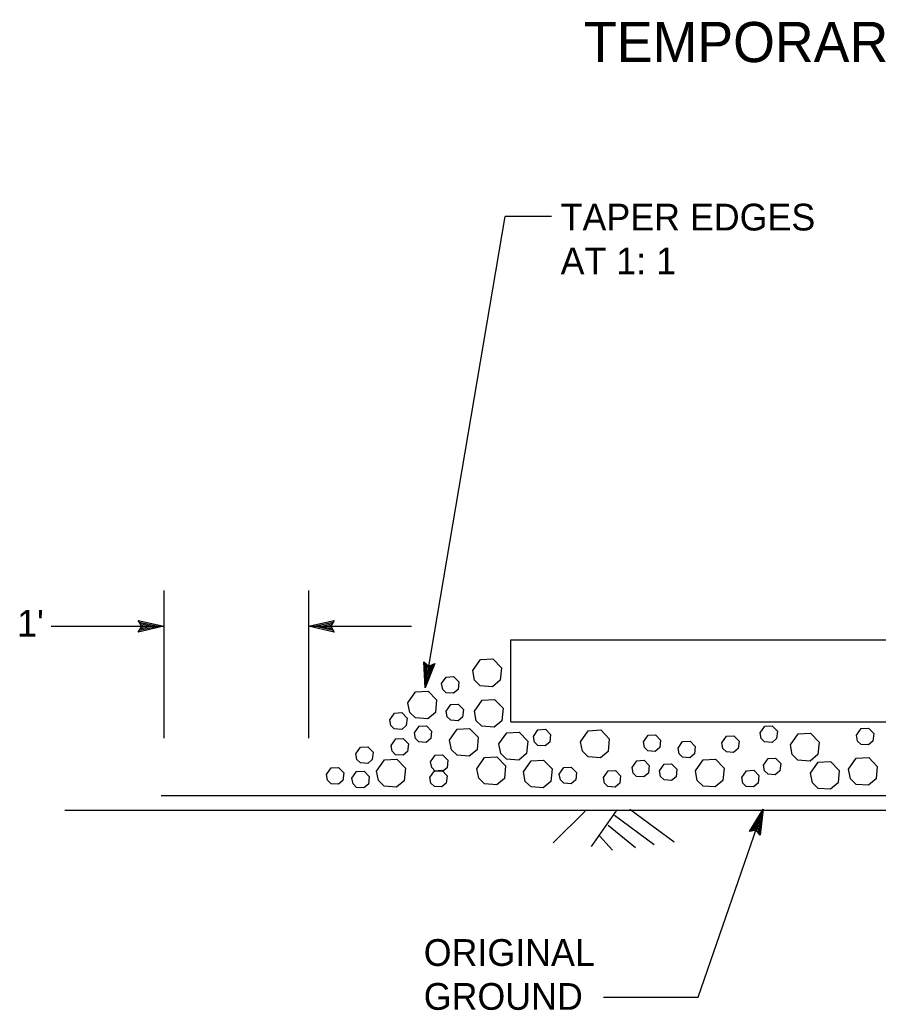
# Model space of a CAD drawing. Extents: x 6709491 to 6710959, y 1869789 to 1870763.
# Drawn here: x 6709492.7 to 6709685, y 1869799.3 to 1870021.3 of the extents above; entities that cross this region are included whole.
import ezdxf

# ---------------------------------------------------------------- set-up
doc = ezdxf.new("R2010")
doc.units = 0
for name, color, linetype in [('56 Stg 3 Anno', 7, 'Continuous'), ('57 Undefined', 7, 'Continuous'), ('59 Soundwall Ann', 7, 'Continuous'), ('60 Nongeo Data', 7, 'Continuous')]:
    doc.layers.add(name, color=color, linetype=linetype)

msp = doc.modelspace()

# ---------------------------------------------------------------- linework, layer by layer
at = {"layer": '56 Stg 3 Anno'}
for p, q in [((6709583.47, 1869871.52), (6709601.41, 1869977.17)), ((6709611.8, 1869977.17), (6709601.41, 1869977.17)), ((6709524.96, 1869893.38), (6709524.96, 1869860.25)), ((6709557.38, 1869893.38), (6709557.38, 1869860.25)), ((6709499.65, 1869885.34), (6709524.96, 1869885.34)), ((6709519.97, 1869885.34), (6709519.2, 1869886.62)), ((6709519.2, 1869886.62), (6709519.2, 1869886.62)), ((6709519.2, 1869886.62), (6709524.96, 1869885.34)), ((6709524.96, 1869885.34), (6709519.2, 1869884.06)), ((6709519.2, 1869884.06), (6709519.97, 1869885.34)), ((6709519.41, 1869886.28), (6709523.64, 1869885.34)), ((6709523.63, 1869885.33), (6709519.43, 1869884.4)), ((6709522.31, 1869885.34), (6709519.6, 1869884.74)), ((6709519.64, 1869885.94), (6709522.31, 1869885.34)), ((6709519.81, 1869885.6), (6709520.99, 1869885.34)), ((6709520.99, 1869885.34), (6709519.82, 1869885.08)), ((6709524.96, 1869885.34), (6709524.96, 1869885.34)), ((6709557.38, 1869885.34), (6709563.14, 1869886.61)), ((6709557.38, 1869885.34), (6709580.43, 1869885.34)), ((6709563.14, 1869884.05), (6709557.38, 1869885.34)), ((6709557.38, 1869885.34), (6709557.38, 1869885.34)), ((6709562.94, 1869884.39), (6709558.71, 1869885.34)), ((6709558.72, 1869885.34), (6709562.92, 1869886.27)), ((6709560.04, 1869885.33), (6709562.75, 1869885.94)), ((6709562.71, 1869884.74), (6709560.04, 1869885.33)), ((6709561.36, 1869885.33), (6709562.52, 1869885.59)), ((6709562.54, 1869885.07), (6709561.36, 1869885.33)), ((6709563.14, 1869886.61), (6709562.38, 1869885.34)), ((6709562.38, 1869885.34), (6709563.14, 1869884.05)), ((6709563.14, 1869886.61), (6709563.14, 1869886.61)), ((6709519.2, 1869884.06), (6709519.2, 1869884.06)), ((6709563.14, 1869884.05), (6709563.14, 1869884.05)), ((6709583.47, 1869871.52), (6709583.17, 1869877.41)), ((6709583.17, 1869877.41), (6709583.17, 1869877.41)), ((6709583.17, 1869877.41), (6709584.3, 1869876.44)), ((6709585.7, 1869876.99), (6709583.47, 1869871.52)), ((6709583.69, 1869872.84), (6709583.48, 1869877.13)), ((6709585.33, 1869876.84), (6709583.69, 1869872.83)), ((6709583.91, 1869874.14), (6709583.78, 1869876.91)), ((6709584.95, 1869876.67), (6709583.91, 1869874.14)), ((6709584.14, 1869875.44), (6709584.08, 1869876.63)), ((6709584.6, 1869876.56), (6709584.14, 1869875.44)), ((6709584.3, 1869876.44), (6709585.7, 1869876.99)), ((6709585.7, 1869876.99), (6709585.7, 1869876.99)), ((6709583.47, 1869871.52), (6709583.47, 1869871.52)), ((6709644.67, 1869802.22), (6709659.29, 1869844.37)), ((6709656.19, 1869839.35), (6709659.29, 1869844.37)), ((6709656.58, 1869839.44), (6709658.85, 1869843.12)), ((6709658.85, 1869843.11), (6709658.36, 1869838.84)), ((6709659.29, 1869844.37), (6709658.61, 1869838.51)), ((6709659.29, 1869844.37), (6709659.29, 1869844.37)), ((6709656.98, 1869839.54), (6709658.42, 1869841.87)), ((6709658.42, 1869841.87), (6709658.1, 1869839.11)), ((6709657.65, 1869839.66), (6709656.19, 1869839.35)), ((6709656.19, 1869839.35), (6709656.19, 1869839.35)), ((6709657.35, 1869839.59), (6709657.98, 1869840.62)), ((6709658.61, 1869838.51), (6709657.65, 1869839.66)), ((6709657.98, 1869840.62), (6709657.84, 1869839.44)), ((6709658.61, 1869838.51), (6709658.61, 1869838.51)), ((6709623.47, 1869802.22), (6709644.67, 1869802.22))]:
    msp.add_line(p, q, dxfattribs=at)
at = {"layer": '59 Soundwall Ann'}
for p, q in [((6709619.34, 1869843.9), (6709612.17, 1869836.78)), ((6709626.49, 1869844.23), (6709620.7, 1869835.99)), ((6709629.39, 1869844.36), (6709639.34, 1869837.03)), ((6709625.94, 1869843.01), (6709634.84, 1869836.46)), ((6709624.5, 1869840.75), (6709630.61, 1869835.77)), ((6709622.56, 1869838.37), (6709625.47, 1869835.17))]:
    msp.add_line(p, q, dxfattribs=at)
at = {"layer": '60 Nongeo Data'}
for p, q in [((6709602.72, 1869863.92), (6709602.72, 1869882.28)), ((6709602.72, 1869882.28), (6709947.32, 1869882.28)), ((6709602.72, 1869863.92), (6709756.24, 1869863.92)), ((6709524.37, 1869847.39), (6709755.52, 1869847.39)), ((6709502.72, 1869844.14), (6709754.44, 1869844.14))]:
    msp.add_line(p, q, dxfattribs=at)
for points in [[(6709594.15, 1869875.41), (6709595.89, 1869877.88), (6709598.67, 1869878.04), (6709600.6, 1869876.04), (6709600.32, 1869873.24), (6709598.6, 1869871.81), (6709595.86, 1869872.01), (6709594.57, 1869873.26), (6709594.15, 1869875.41)], [(6709587.18, 1869872.5), (6709588.23, 1869873.98), (6709589.89, 1869874.08), (6709591.05, 1869872.87), (6709590.88, 1869871.19), (6709589.85, 1869870.34), (6709588.21, 1869870.45), (6709587.43, 1869871.2), (6709587.18, 1869872.5)], [(6709579.62, 1869868.2), (6709581.36, 1869870.67), (6709584.14, 1869870.83), (6709586.07, 1869868.83), (6709585.79, 1869866.02), (6709584.07, 1869864.6), (6709581.33, 1869864.8), (6709580.04, 1869866.05), (6709579.62, 1869868.2)], [(6709588.2, 1869866.31), (6709589.24, 1869867.8), (6709590.91, 1869867.89), (6709592.07, 1869866.69), (6709591.9, 1869865.01), (6709590.87, 1869864.15), (6709589.22, 1869864.27), (6709588.45, 1869865.02), (6709588.2, 1869866.31)], [(6709594.53, 1869866.33), (6709596.27, 1869868.81), (6709599.04, 1869868.97), (6709600.98, 1869866.97), (6709600.7, 1869864.16), (6709598.98, 1869862.73), (6709596.24, 1869862.93), (6709594.95, 1869864.18), (6709594.53, 1869866.33)], [(6709575.57, 1869864.41), (6709576.61, 1869865.89), (6709578.28, 1869865.99), (6709579.44, 1869864.78), (6709579.27, 1869863.1), (6709578.24, 1869862.25), (6709576.59, 1869862.36), (6709575.82, 1869863.11), (6709575.57, 1869864.41)], [(6709581.08, 1869861.48), (6709582.13, 1869862.97), (6709583.79, 1869863.06), (6709584.95, 1869861.86), (6709584.78, 1869860.18), (6709583.76, 1869859.32), (6709582.11, 1869859.44), (6709581.34, 1869860.19), (6709581.09, 1869861.48)], [(6709658.57, 1869861.48), (6709659.61, 1869862.97), (6709661.28, 1869863.06), (6709662.44, 1869861.86), (6709662.27, 1869860.18), (6709661.24, 1869859.32), (6709659.59, 1869859.44), (6709658.82, 1869860.19), (6709658.57, 1869861.48)], [(6709588.95, 1869859.84), (6709590.69, 1869862.31), (6709593.46, 1869862.47), (6709595.39, 1869860.47), (6709595.12, 1869857.66), (6709593.4, 1869856.23), (6709590.66, 1869856.43), (6709589.37, 1869857.69), (6709588.95, 1869859.84)], [(6709600.04, 1869858.97), (6709601.78, 1869861.44), (6709604.56, 1869861.6), (6709606.49, 1869859.6), (6709606.21, 1869856.8), (6709604.5, 1869855.37), (6709601.75, 1869855.57), (6709600.46, 1869856.82), (6709600.05, 1869858.97)], [(6709607.75, 1869860.68), (6709608.79, 1869862.16), (6709610.46, 1869862.26), (6709611.61, 1869861.06), (6709611.45, 1869859.38), (6709610.42, 1869858.52), (6709608.77, 1869858.64), (6709608, 1869859.39), (6709607.75, 1869860.68)], [(6709618.33, 1869859.48), (6709620.07, 1869861.95), (6709622.84, 1869862.11), (6709624.77, 1869860.11), (6709624.5, 1869857.3), (6709622.78, 1869855.88), (6709620.04, 1869856.08), (6709618.75, 1869857.33), (6709618.33, 1869859.48)], [(6709632.41, 1869859.47), (6709633.45, 1869860.95), (6709635.12, 1869861.05), (6709636.27, 1869859.85), (6709636.11, 1869858.16), (6709635.08, 1869857.31), (6709633.43, 1869857.43), (6709632.66, 1869858.18), (6709632.41, 1869859.47)], [(6709649.97, 1869859.24), (6709651.01, 1869860.73), (6709652.68, 1869860.82), (6709653.84, 1869859.62), (6709653.67, 1869857.94), (6709652.64, 1869857.08), (6709651, 1869857.2), (6709650.22, 1869857.95), (6709649.97, 1869859.24)], [(6709665.35, 1869858.75), (6709667.09, 1869861.23), (6709669.87, 1869861.39), (6709671.8, 1869859.38), (6709671.52, 1869856.58), (6709669.8, 1869855.15), (6709667.06, 1869855.35), (6709665.77, 1869856.6), (6709665.35, 1869858.75)], [(6709680.16, 1869860.93), (6709681.21, 1869862.41), (6709682.87, 1869862.51), (6709684.03, 1869861.3), (6709683.86, 1869859.62), (6709682.84, 1869858.77), (6709681.19, 1869858.88), (6709680.42, 1869859.63), (6709680.17, 1869860.93)], [(6709575.87, 1869858.61), (6709576.91, 1869860.1), (6709578.58, 1869860.19), (6709579.74, 1869858.99), (6709579.57, 1869857.31), (6709578.54, 1869856.45), (6709576.89, 1869856.57), (6709576.12, 1869857.32), (6709575.87, 1869858.61)], [(6709640.17, 1869858.04), (6709641.21, 1869859.52), (6709642.88, 1869859.62), (6709644.04, 1869858.42), (6709643.87, 1869856.74), (6709642.84, 1869855.88), (6709641.19, 1869856), (6709640.42, 1869856.75), (6709640.17, 1869858.04)], [(6709567.96, 1869856.78), (6709569, 1869858.26), (6709570.67, 1869858.36), (6709571.83, 1869857.16), (6709571.66, 1869855.48), (6709570.63, 1869854.62), (6709568.99, 1869854.74), (6709568.21, 1869855.49), (6709567.96, 1869856.78)], [(6709584.71, 1869854.95), (6709585.75, 1869856.44), (6709587.42, 1869856.53), (6709588.58, 1869855.33), (6709588.41, 1869853.65), (6709587.38, 1869852.79), (6709585.74, 1869852.91), (6709584.96, 1869853.66), (6709584.71, 1869854.95)], [(6709572.62, 1869852.91), (6709574.36, 1869855.39), (6709577.13, 1869855.55), (6709579.07, 1869853.54), (6709578.79, 1869850.74), (6709577.07, 1869849.31), (6709574.33, 1869849.51), (6709573.04, 1869850.76), (6709572.62, 1869852.91)], [(6709595.08, 1869853.42), (6709596.82, 1869855.9), (6709599.59, 1869856.06), (6709601.52, 1869854.06), (6709601.25, 1869851.25), (6709599.53, 1869849.82), (6709596.79, 1869850.02), (6709595.5, 1869851.27), (6709595.08, 1869853.42)], [(6709605.52, 1869852.73), (6709607.26, 1869855.2), (6709610.04, 1869855.36), (6709611.97, 1869853.36), (6709611.69, 1869850.55), (6709609.98, 1869849.13), (6709607.23, 1869849.33), (6709605.94, 1869850.58), (6709605.52, 1869852.73)], [(6709629.87, 1869853.73), (6709630.91, 1869855.21), (6709632.58, 1869855.31), (6709633.74, 1869854.11), (6709633.57, 1869852.42), (6709632.54, 1869851.57), (6709630.89, 1869851.68), (6709630.12, 1869852.44), (6709629.87, 1869853.73)], [(6709636.03, 1869852.94), (6709637.08, 1869854.42), (6709638.74, 1869854.52), (6709639.9, 1869853.32), (6709639.73, 1869851.63), (6709638.7, 1869850.78), (6709637.06, 1869850.9), (6709636.28, 1869851.65), (6709636.03, 1869852.94)], [(6709644.06, 1869852.94), (6709645.8, 1869855.41), (6709648.58, 1869855.57), (6709650.51, 1869853.57), (6709650.23, 1869850.76), (6709648.51, 1869849.34), (6709645.77, 1869849.54), (6709644.48, 1869850.79), (6709644.06, 1869852.94)], [(6709659.31, 1869854.23), (6709660.36, 1869855.71), (6709662.02, 1869855.81), (6709663.18, 1869854.61), (6709663.01, 1869852.93), (6709661.98, 1869852.07), (6709660.34, 1869852.19), (6709659.56, 1869852.94), (6709659.31, 1869854.23)], [(6709669.86, 1869852.42), (6709671.6, 1869854.9), (6709674.38, 1869855.06), (6709676.31, 1869853.06), (6709676.03, 1869850.25), (6709674.32, 1869848.82), (6709671.57, 1869849.02), (6709670.28, 1869850.27), (6709669.86, 1869852.42)], [(6709678.39, 1869853.31), (6709680.13, 1869855.78), (6709682.9, 1869855.94), (6709684.83, 1869853.94), (6709684.55, 1869851.13), (6709682.84, 1869849.71), (6709680.1, 1869849.9), (6709678.81, 1869851.16), (6709678.39, 1869853.31)], [(6709561.38, 1869852.11), (6709562.42, 1869853.59), (6709564.09, 1869853.69), (6709565.25, 1869852.49), (6709565.08, 1869850.8), (6709564.05, 1869849.95), (6709562.41, 1869850.07), (6709561.63, 1869850.82), (6709561.38, 1869852.11)], [(6709567.1, 1869851.29), (6709568.14, 1869852.77), (6709569.81, 1869852.87), (6709570.97, 1869851.66), (6709570.8, 1869849.98), (6709569.77, 1869849.13), (6709568.13, 1869849.24), (6709567.35, 1869850), (6709567.1, 1869851.29)], [(6709584.54, 1869851.49), (6709585.58, 1869852.97), (6709587.25, 1869853.07), (6709588.41, 1869851.86), (6709588.24, 1869850.18), (6709587.21, 1869849.33), (6709585.56, 1869849.44), (6709584.79, 1869850.2), (6709584.54, 1869851.49)], [(6709613.55, 1869852.21), (6709614.59, 1869853.7), (6709616.26, 1869853.79), (6709617.42, 1869852.59), (6709617.25, 1869850.91), (6709616.22, 1869850.05), (6709614.57, 1869850.17), (6709613.8, 1869850.92), (6709613.55, 1869852.21)], [(6709623.44, 1869851.45), (6709624.49, 1869852.94), (6709626.15, 1869853.03), (6709627.31, 1869851.83), (6709627.14, 1869850.15), (6709626.11, 1869849.29), (6709624.47, 1869849.41), (6709623.7, 1869850.16), (6709623.44, 1869851.45)], [(6709654.45, 1869851.49), (6709655.5, 1869852.97), (6709657.16, 1869853.07), (6709658.32, 1869851.87), (6709658.15, 1869850.18), (6709657.12, 1869849.33), (6709655.48, 1869849.44), (6709654.71, 1869850.2), (6709654.45, 1869851.49)]]:
    msp.add_lwpolyline(points, dxfattribs=at)

# ---------------------------------------------------------------- texts
at = {"layer": '57 Undefined'}
for s, height, p in [('TEMPORARY CONSTRUCTION ENTRANCE (TYPE 2)', 9, (6709619.09, 1870011.81)), ('TAPER EDGES', 6, (6709613.86, 1869974.07)), ('AT 1: 1', 6, (6709613.86, 1869964.23)), ("1'", 6, (6709492.05, 1869883.02)), ('ORIGINAL', 6, (6709583.18, 1869809.22)), ('GROUND', 6, (6709583.18, 1869799.38))]:
    msp.add_text(s, height=height, dxfattribs=at).set_placement(p)

doc.saveas('drawing.dxf')
